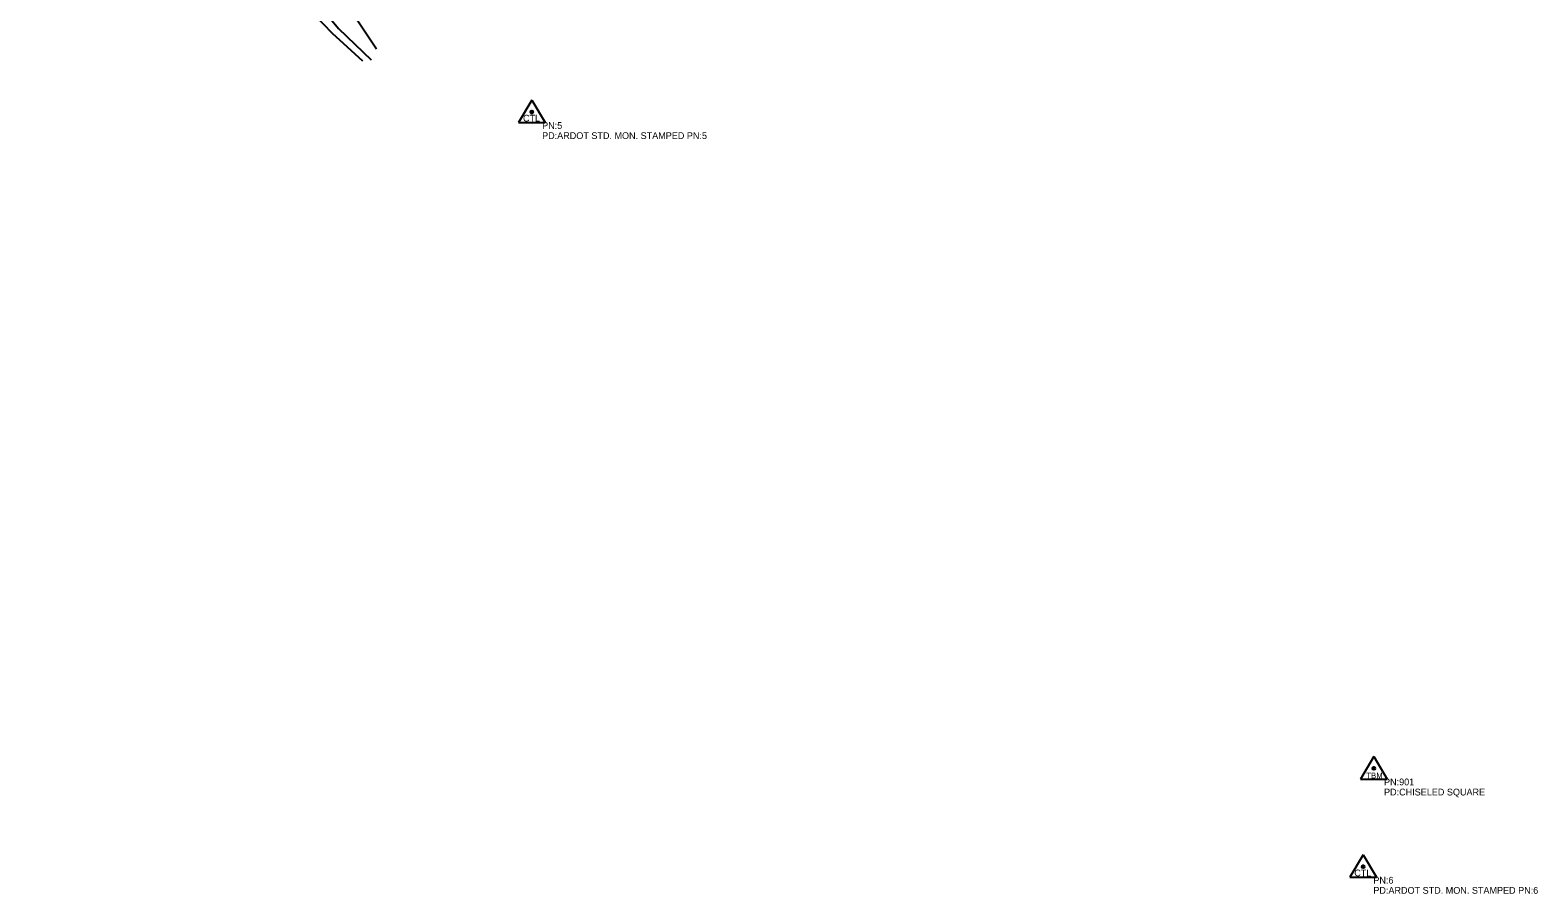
# Model space of a CAD drawing. Extents: x 1193883 to 1197064, y 1474583 to 1477379.
# Drawn here: x 1195950 to 1197064, y 1474583 to 1475221 of the extents above; entities that cross this region are included whole.
import ezdxf

# ---------------------------------------------------------------- set-up
doc = ezdxf.new("R2010")
doc.units = 0
for name, color, linetype in [('S_DITCHLINE', 7, 'Continuous'), ('S_LEVEE', 7, 'Continuous'), ('S_PRIMARY_CTL', 7, 'Continuous'), ('S_PRIMARY_CTL_ANNOT', 7, 'Continuous')]:
    doc.layers.add(name, color=color, linetype=linetype)

msp = doc.modelspace()

# ---------------------------------------------------------------- linework, layer by layer
at = {"layer": 'S_DITCHLINE'}
msp.add_lwpolyline([(1196187.9, 1475233.8), (1196196.9, 1475220.5), (1196205.8, 1475207.2)], dxfattribs=at)
at = {"layer": 'S_LEVEE'}
for points in [[(1195949.8, 1475420.9), (1195971.8, 1475416.9), (1195986.1, 1475404.1), (1196000.3, 1475391.3), (1196014.6, 1475378.5), (1196028.9, 1475365.7), (1196045.5, 1475350.5), (1196062.2, 1475335.3), (1196074.9, 1475323.4), (1196087.7, 1475311.6), (1196100.4, 1475299.7), (1196113.2, 1475287.8), (1196126.8, 1475269.2), (1196136.7, 1475257.7), (1196146.5, 1475246.2), (1196159.7, 1475232.4), (1196172.9, 1475218.6), (1196184.1, 1475208.5), (1196195.3, 1475198.3)], [(1195955.5, 1475427.3), (1195975.1, 1475422.8), (1195988.4, 1475411.3), (1196001.6, 1475399.8), (1196014.9, 1475388.3), (1196028.2, 1475376.7), (1196043.9, 1475361.6), (1196059.5, 1475346.5), (1196074.3, 1475332.6), (1196089, 1475318.6), (1196103.7, 1475304.6), (1196118.4, 1475290.6), (1196132.3, 1475273.3), (1196141.6, 1475263.7), (1196151, 1475254.1), (1196164.3, 1475238.1), (1196177.6, 1475222.1), (1196189.6, 1475210.5), (1196201.7, 1475198.9)]]:
    msp.add_lwpolyline(points, dxfattribs=at)
at = {"layer": 'S_PRIMARY_CTL'}
for p, q in [((1196320.6, 1475169.2), (1196310.6, 1475152.6)), ((1196320.6, 1475169.2), (1196330.4, 1475152.6)), ((1196310.6, 1475152.6), (1196330.4, 1475152.6)), ((1196942.8, 1474684.4), (1196932.8, 1474667.8)), ((1196942.8, 1474684.4), (1196952.6, 1474667.8)), ((1196932.8, 1474667.8), (1196952.6, 1474667.8)), ((1196934.9, 1474611.8), (1196924.9, 1474595.3)), ((1196934.9, 1474611.8), (1196944.7, 1474595.3)), ((1196924.9, 1474595.3), (1196944.7, 1474595.3))]:
    msp.add_line(p, q, dxfattribs=at)
for centre, radius in [((1196320.6, 1475160.5), 1.04), ((1196320.6, 1475160.5), 0.609), ((1196320.6, 1475160.5), 0.344), ((1196942.8, 1474675.7), 1.04), ((1196942.8, 1474675.7), 0.609), ((1196942.8, 1474675.7), 0.344), ((1196934.9, 1474603.1), 1.04), ((1196934.9, 1474603.1), 0.609), ((1196934.9, 1474603.1), 0.344)]:
    msp.add_circle(centre, radius, dxfattribs=at)

# ---------------------------------------------------------------- texts
for s, height, p in [('CTL', 5, (1196314, 1475153.4)), ('TBM', 4.29, (1196937.2, 1474668.3)), ('CTL', 5, (1196928.3, 1474596))]:
    msp.add_text(s, height=height, rotation=360, dxfattribs=at).set_placement(p)
at = {"layer": 'S_PRIMARY_CTL_ANNOT'}
for s, p in [('PN:5', (1196328.1, 1475148)), ('PD:ARDOT STD. MON. STAMPED PN:5', (1196328.1, 1475140.5)), ('PN:901', (1196950.3, 1474663.2)), ('PD:CHISELED SQUARE', (1196950.3, 1474655.7)), ('PN:6', (1196942.4, 1474590.6)), ('PD:ARDOT STD. MON. STAMPED PN:6', (1196942.4, 1474583.1))]:
    msp.add_text(s, height=5, dxfattribs=at).set_placement(p)

doc.saveas('drawing.dxf')
